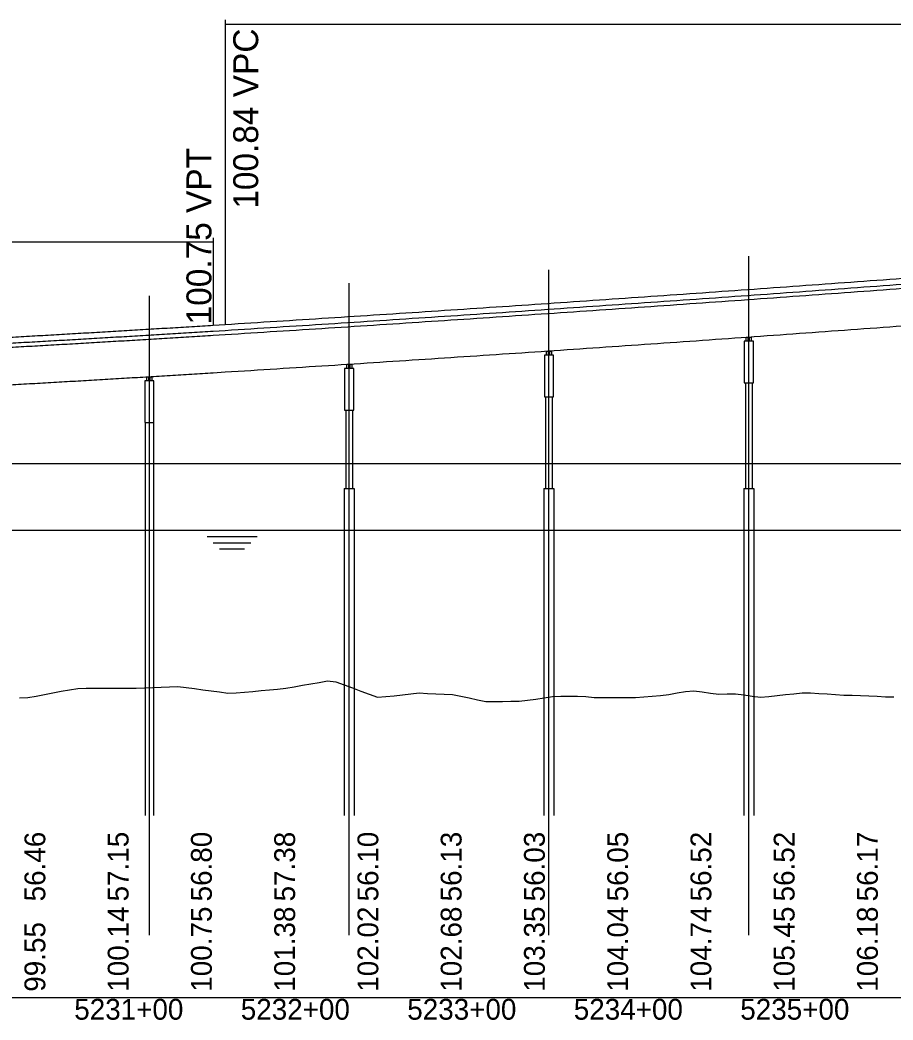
# Model space of a CAD drawing. Extents: x 2121671 to 2169879, y 557274 to 599957.
# Drawn here: x 2152602 to 2153126, y 579173 to 579774 of the extents above; entities that cross this region are included whole.
import ezdxf

# ---------------------------------------------------------------- set-up
doc = ezdxf.new("R2010")
doc.units = 0
for name, color, linetype in [('BR_CENTER LINES', 7, 'Continuous'), ('BR_CONCRETE', 7, 'Continuous'), ('BR_DETAILS', 7, 'Continuous'), ('BR_PRESTRESSED BEAM', 7, 'Continuous'), ('RD_DDB_Profile_Elev', 7, 'Continuous'), ('RD_DDB_Profile_EX', 7, 'Continuous'), ('RD_DDB_Profile_PR', 7, 'Continuous'), ('RD_DDB_StaTX', 7, 'Continuous'), ('RD_DDB_StripGrade', 7, 'Continuous'), ('RD_DDB_VCLbl', 7, 'Continuous'), ('RD_GPK_Profile_Cell', 7, 'Continuous')]:
    doc.layers.add(name, color=color, linetype=linetype)

msp = doc.modelspace()

# ---------------------------------------------------------------- linework, layer by layer
at = {"layer": 'BR_CENTER LINES'}
for p, q in [((2153039.43, 579224.3), (2153039.43, 579632.04)), ((2152919.43, 579224.3), (2152919.43, 579623.69)), ((2152799.43, 579224.3), (2152799.43, 579615.74)), ((2152679.43, 579224.3), (2152679.43, 579608.2))]:
    msp.add_line(p, q, dxfattribs=at)
at = {"layer": 'BR_CONCRETE'}
for p, q in [((2152717.84, 579587.02), (2152724.93, 579587.46)), ((2153037.43, 579555.89), (2153037.43, 579492.43)), ((2153041.43, 579555.89), (2153041.43, 579492.43)), ((2152917.43, 579547.54), (2152917.43, 579492.43)), ((2152921.43, 579547.54), (2152921.43, 579492.43)), ((2152797.43, 579539.6), (2152797.43, 579492.43)), ((2152801.43, 579539.6), (2152801.43, 579492.43)), ((2152676.93, 579532.07), (2152676.93, 579296.09)), ((2152681.93, 579532.07), (2152681.93, 579296.09)), ((2152796.43, 579492.43), (2152796.43, 579296.09)), ((2152796.43, 579492.43), (2152802.43, 579492.43)), ((2152802.43, 579492.43), (2152802.43, 579296.09)), ((2152916.43, 579492.43), (2152916.43, 579296.09)), ((2152916.43, 579492.43), (2152922.43, 579492.43)), ((2152922.43, 579492.43), (2152922.43, 579296.09)), ((2153036.43, 579492.43), (2153036.43, 579296.09)), ((2153036.43, 579492.43), (2153042.43, 579492.43)), ((2153042.43, 579492.43), (2153042.43, 579296.09))]:
    msp.add_line(p, q, dxfattribs=at)
for points in [[(2153036.68, 579555.89), (2153042.18, 579555.89), (2153042.18, 579580.89), (2153036.68, 579580.89)], [(2152916.68, 579547.54), (2152922.18, 579547.54), (2152922.18, 579572.54), (2152916.68, 579572.54)], [(2152796.68, 579539.6), (2152802.18, 579539.6), (2152802.18, 579564.6), (2152796.68, 579564.6)], [(2152676.68, 579532.07), (2152682.18, 579532.07), (2152682.18, 579557.07), (2152676.68, 579557.07)]]:
    msp.add_lwpolyline(points, close=True, dxfattribs=at)
for points in [[(2152724.93, 579587.46), (2152755.93, 579589.42), (2152786.93, 579591.39), (2152817.93, 579593.4), (2152848.93, 579595.43), (2152879.93, 579597.48), (2152910.93, 579599.57), (2152941.93, 579601.68), (2152972.93, 579603.82), (2153003.93, 579605.98), (2153034.93, 579608.17), (2153065.93, 579610.39), (2153096.93, 579612.64), (2153127.93, 579614.91), (2153158.93, 579617.21), (2153189.93, 579619.53), (2153220.93, 579621.88), (2153251.93, 579624.26), (2153282.93, 579626.67), (2153313.93, 579629.1), (2153344.93, 579631.56), (2153375.93, 579634.04), (2153406.93, 579636.55), (2153437.93, 579639.09), (2153468.93, 579641.66), (2153499.93, 579644.25), (2153530.93, 579646.87), (2153561.93, 579649.52), (2153592.93, 579652.19), (2153623.93, 579654.89), (2153654.93, 579657.61), (2153685.93, 579660.37), (2153716.93, 579663.15), (2153747.93, 579665.95), (2153778.93, 579668.79), (2153809.93, 579671.65), (2153840.93, 579674.53), (2153871.93, 579677.45), (2153902.93, 579680.39), (2153933.93, 579683.35), (2153964.93, 579686.35), (2153995.93, 579689.37), (2154026.93, 579692.42), (2154057.93, 579695.49), (2154088.93, 579698.59), (2154119.93, 579701.72), (2154150.93, 579704.87), (2154181.93, 579708.05), (2154212.93, 579711.26), (2154243.93, 579714.5), (2154274.93, 579717.76)], [(2152067.84, 579557.94), (2152080.84, 579558.29), (2152093.84, 579558.66), (2152106.84, 579559.03), (2152119.84, 579559.42), (2152132.84, 579559.81), (2152145.84, 579560.21), (2152158.84, 579560.62), (2152171.84, 579561.04), (2152184.84, 579561.47), (2152197.84, 579561.91), (2152210.84, 579562.36), (2152223.84, 579562.82), (2152236.84, 579563.28), (2152249.84, 579563.76), (2152262.84, 579564.24), (2152275.84, 579564.74), (2152288.84, 579565.24), (2152301.84, 579565.75), (2152314.84, 579566.27), (2152327.84, 579566.8), (2152340.84, 579567.34), (2152353.84, 579567.89), (2152366.84, 579568.45), (2152379.84, 579569.02), (2152392.84, 579569.6), (2152405.84, 579570.18), (2152418.84, 579570.78), (2152431.84, 579571.38), (2152444.84, 579572), (2152457.84, 579572.62), (2152470.84, 579573.25), (2152483.84, 579573.89), (2152496.84, 579574.55), (2152509.84, 579575.21), (2152522.84, 579575.87), (2152535.84, 579576.55), (2152548.84, 579577.24), (2152561.84, 579577.94), (2152574.84, 579578.64), (2152587.84, 579579.36), (2152600.84, 579580.08), (2152613.84, 579580.82), (2152626.84, 579581.56), (2152639.84, 579582.31), (2152652.84, 579583.08), (2152665.84, 579583.85), (2152678.84, 579584.63), (2152691.84, 579585.42), (2152704.84, 579586.21), (2152717.84, 579587.02)]]:
    msp.add_spline(points, degree=3, dxfattribs=at)
at = {"layer": 'BR_DETAILS'}
for points in [[(2153037.93, 579583.39), (2153038.93, 579583.39), (2153038.93, 579580.89), (2153037.93, 579580.89)], [(2153039.93, 579583.39), (2153040.93, 579583.39), (2153040.93, 579580.89), (2153039.93, 579580.89)], [(2152917.93, 579575.04), (2152918.93, 579575.04), (2152918.93, 579572.54), (2152917.93, 579572.54)], [(2152919.93, 579575.04), (2152920.93, 579575.04), (2152920.93, 579572.54), (2152919.93, 579572.54)], [(2152797.93, 579567.1), (2152798.93, 579567.1), (2152798.93, 579564.6), (2152797.93, 579564.6)], [(2152799.93, 579567.1), (2152800.93, 579567.1), (2152800.93, 579564.6), (2152799.93, 579564.6)], [(2152677.93, 579559.57), (2152678.93, 579559.57), (2152678.93, 579557.07), (2152677.93, 579557.07)], [(2152679.93, 579559.57), (2152680.93, 579559.57), (2152680.93, 579557.07), (2152679.93, 579557.07)]]:
    msp.add_lwpolyline(points, close=True, dxfattribs=at)
at = {"layer": 'BR_PRESTRESSED BEAM'}
for p, q in [((2152717.84, 579584.52), (2152724.93, 579584.96)), ((2152717.84, 579562.02), (2152724.93, 579562.46))]:
    msp.add_line(p, q, dxfattribs=at)
for points in [[(2152724.93, 579584.96), (2152755.93, 579586.92), (2152786.93, 579588.89), (2152817.93, 579590.9), (2152848.93, 579592.93), (2152879.93, 579594.98), (2152910.93, 579597.07), (2152941.93, 579599.18), (2152972.93, 579601.32), (2153003.93, 579603.48), (2153034.93, 579605.67), (2153065.93, 579607.89), (2153096.93, 579610.14), (2153127.93, 579612.41), (2153158.93, 579614.71), (2153189.93, 579617.03), (2153220.93, 579619.38), (2153251.93, 579621.76), (2153282.93, 579624.17), (2153313.93, 579626.6), (2153344.93, 579629.06), (2153375.93, 579631.54), (2153406.93, 579634.05), (2153437.93, 579636.59), (2153468.93, 579639.16), (2153499.93, 579641.75), (2153530.93, 579644.37), (2153561.93, 579647.02), (2153592.93, 579649.69), (2153623.93, 579652.39), (2153654.93, 579655.11), (2153685.93, 579657.87), (2153716.93, 579660.65), (2153747.93, 579663.45), (2153778.93, 579666.29), (2153809.93, 579669.15), (2153840.93, 579672.03), (2153871.93, 579674.95), (2153902.93, 579677.89), (2153933.93, 579680.85), (2153964.93, 579683.85), (2153995.93, 579686.87), (2154026.93, 579689.92), (2154057.93, 579692.99), (2154088.93, 579696.09), (2154119.93, 579699.22), (2154150.93, 579702.37), (2154181.93, 579705.55), (2154212.93, 579708.76), (2154243.93, 579712), (2154274.93, 579715.26)], [(2152724.93, 579562.46), (2152755.93, 579564.42), (2152786.93, 579566.39), (2152817.93, 579568.4), (2152848.93, 579570.43), (2152879.93, 579572.48), (2152910.93, 579574.57), (2152941.93, 579576.68), (2152972.93, 579578.82), (2153003.93, 579580.98), (2153034.93, 579583.17), (2153065.93, 579585.39), (2153096.93, 579587.64), (2153127.93, 579589.91), (2153158.93, 579592.21), (2153189.93, 579594.53), (2153220.93, 579596.88), (2153251.93, 579599.26), (2153282.93, 579601.67), (2153313.93, 579604.1), (2153344.93, 579606.56), (2153375.93, 579609.04), (2153406.93, 579611.55), (2153437.93, 579614.09), (2153468.93, 579616.66), (2153499.93, 579619.25), (2153530.93, 579621.87), (2153561.93, 579624.52), (2153592.93, 579627.19), (2153623.93, 579629.89), (2153654.93, 579632.61), (2153685.93, 579635.37), (2153716.93, 579638.15), (2153747.93, 579640.95), (2153778.93, 579643.79), (2153809.93, 579646.65), (2153840.93, 579649.53), (2153871.93, 579652.45), (2153902.93, 579655.39), (2153933.93, 579658.35), (2153964.93, 579661.35), (2153995.93, 579664.37), (2154026.93, 579667.42), (2154057.93, 579670.49), (2154088.93, 579673.59), (2154119.93, 579676.72), (2154150.93, 579679.87), (2154181.93, 579683.05), (2154212.93, 579686.26), (2154243.93, 579689.5), (2154274.93, 579692.76)], [(2152067.84, 579555.44), (2152080.84, 579555.79), (2152093.84, 579556.16), (2152106.84, 579556.53), (2152119.84, 579556.92), (2152132.84, 579557.31), (2152145.84, 579557.71), (2152158.84, 579558.12), (2152171.84, 579558.54), (2152184.84, 579558.97), (2152197.84, 579559.41), (2152210.84, 579559.86), (2152223.84, 579560.32), (2152236.84, 579560.78), (2152249.84, 579561.26), (2152262.84, 579561.74), (2152275.84, 579562.24), (2152288.84, 579562.74), (2152301.84, 579563.25), (2152314.84, 579563.77), (2152327.84, 579564.3), (2152340.84, 579564.84), (2152353.84, 579565.39), (2152366.84, 579565.95), (2152379.84, 579566.52), (2152392.84, 579567.1), (2152405.84, 579567.68), (2152418.84, 579568.28), (2152431.84, 579568.88), (2152444.84, 579569.5), (2152457.84, 579570.12), (2152470.84, 579570.75), (2152483.84, 579571.39), (2152496.84, 579572.05), (2152509.84, 579572.71), (2152522.84, 579573.37), (2152535.84, 579574.05), (2152548.84, 579574.74), (2152561.84, 579575.44), (2152574.84, 579576.14), (2152587.84, 579576.86), (2152600.84, 579577.58), (2152613.84, 579578.32), (2152626.84, 579579.06), (2152639.84, 579579.81), (2152652.84, 579580.58), (2152665.84, 579581.35), (2152678.84, 579582.13), (2152691.84, 579582.92), (2152704.84, 579583.71), (2152717.84, 579584.52)], [(2152067.84, 579532.94), (2152080.84, 579533.29), (2152093.84, 579533.66), (2152106.84, 579534.03), (2152119.84, 579534.42), (2152132.84, 579534.81), (2152145.84, 579535.21), (2152158.84, 579535.62), (2152171.84, 579536.04), (2152184.84, 579536.47), (2152197.84, 579536.91), (2152210.84, 579537.36), (2152223.84, 579537.82), (2152236.84, 579538.28), (2152249.84, 579538.76), (2152262.84, 579539.24), (2152275.84, 579539.74), (2152288.84, 579540.24), (2152301.84, 579540.75), (2152314.84, 579541.27), (2152327.84, 579541.8), (2152340.84, 579542.34), (2152353.84, 579542.89), (2152366.84, 579543.45), (2152379.84, 579544.02), (2152392.84, 579544.6), (2152405.84, 579545.18), (2152418.84, 579545.78), (2152431.84, 579546.38), (2152444.84, 579547), (2152457.84, 579547.62), (2152470.84, 579548.25), (2152483.84, 579548.89), (2152496.84, 579549.55), (2152509.84, 579550.21), (2152522.84, 579550.87), (2152535.84, 579551.55), (2152548.84, 579552.24), (2152561.84, 579552.94), (2152574.84, 579553.64), (2152587.84, 579554.36), (2152600.84, 579555.08), (2152613.84, 579555.82), (2152626.84, 579556.56), (2152639.84, 579557.31), (2152652.84, 579558.08), (2152665.84, 579558.85), (2152678.84, 579559.63), (2152691.84, 579560.42), (2152704.84, 579561.21), (2152717.84, 579562.02)]]:
    msp.add_spline(points, degree=3, dxfattribs=at)
at = {"layer": 'RD_DDB_Profile_Elev'}
for p, q in [((2151922.43, 579507.43), (2155499.43, 579507.43)), ((2151953.51, 579467.43), (2156316.65, 579467.43)), ((2152714.09, 579463.68), (2152744.09, 579463.68)), ((2152717.84, 579459.93), (2152740.34, 579459.93)), ((2152721.59, 579456.18), (2152736.59, 579456.18))]:
    msp.add_line(p, q, dxfattribs=at)
at = {"layer": 'RD_DDB_Profile_EX'}
for points in [[(2152721.48, 579370.34), (2152726.48, 579369.68), (2152731.48, 579369.8), (2152736.48, 579370.24), (2152741.48, 579370.67), (2152746.48, 579371.11), (2152751.48, 579371.54), (2152756.48, 579371.98), (2152761.48, 579372.59), (2152766.48, 579373.46), (2152771.48, 579374.33), (2152776.48, 579375.19), (2152781.48, 579376.06), (2152786.48, 579376.93), (2152791.48, 579376.38), (2152796.48, 579374.55), (2152801.48, 579372.72), (2152806.48, 579370.89), (2152811.48, 579369.06), (2152816.48, 579367.23), (2152821.48, 579367.5), (2152826.48, 579368.08), (2152831.48, 579368.65), (2152836.48, 579369.23), (2152841.48, 579369.72), (2152846.48, 579369.48), (2152851.48, 579369.25), (2152856.48, 579369.02), (2152861.48, 579368.79), (2152866.48, 579367.79), (2152871.48, 579366.73), (2152876.48, 579365.67), (2152881.48, 579364.61), (2152886.48, 579364.54), (2152891.48, 579364.63), (2152896.48, 579364.73), (2152901.48, 579364.82), (2152906.48, 579365.3), (2152911.48, 579366.03), (2152916.48, 579366.76), (2152921.48, 579367.5), (2152926.48, 579367.88), (2152931.48, 579367.8), (2152936.48, 579367.72), (2152941.48, 579367.65), (2152946.48, 579366.91), (2152951.48, 579366.96), (2152956.48, 579367.02), (2152961.48, 579367.07), (2152966.48, 579367.06), (2152971.48, 579367.08), (2152976.48, 579367.44), (2152981.48, 579367.8), (2152986.48, 579368.16), (2152991.48, 579368.87), (2152996.48, 579369.75), (2153001.48, 579370.63), (2153006.48, 579371.07), (2153011.48, 579370.35), (2153016.48, 579369.62), (2153021.48, 579368.9), (2153026.48, 579369.28), (2153031.48, 579369.19), (2153036.48, 579368.53), (2153041.48, 579367.87), (2153046.48, 579367.21), (2153051.48, 579367.66), (2153056.48, 579368.2), (2153061.48, 579368.74), (2153066.48, 579369.29), (2153071.48, 579369.76), (2153076.48, 579369.82), (2153081.48, 579369.48), (2153086.48, 579369.14), (2153091.48, 579368.8), (2153096.48, 579368.46), (2153101.48, 579368.46), (2153106.48, 579368.21), (2153111.48, 579367.97), (2153116.48, 579367.73), (2153121.48, 579367.48), (2153126.48, 579367.37)], [(2152601.48, 579366.77), (2152606.48, 579366.92), (2152611.48, 579367.88), (2152616.48, 579368.83), (2152621.48, 579369.78), (2152626.48, 579370.74), (2152631.48, 579371.69), (2152636.48, 579372.5), (2152641.48, 579372.54), (2152646.48, 579372.57), (2152651.48, 579372.6), (2152656.48, 579372.63), (2152661.48, 579372.66), (2152666.48, 579372.56), (2152671.48, 579372.65), (2152676.48, 579372.83), (2152681.48, 579373), (2152686.48, 579373.18), (2152691.48, 579373.35), (2152696.48, 579373.53), (2152701.48, 579372.98), (2152706.48, 579372.32), (2152711.48, 579371.66), (2152716.48, 579371), (2152721.48, 579370.34)]]:
    msp.add_lwpolyline(points, dxfattribs=at)
at = {"layer": 'RD_DDB_Profile_PR'}
msp.add_line((2152717.84, 579590.56), (2152724.93, 579591.01), dxfattribs=at)
for points in [[(2152724.93, 579591.01), (2152755.93, 579592.96), (2152786.93, 579594.93), (2152817.93, 579596.94), (2152848.93, 579598.97), (2152879.93, 579601.03), (2152910.93, 579603.11), (2152941.93, 579605.22), (2152972.93, 579607.36), (2153003.93, 579609.52), (2153034.93, 579611.71), (2153065.93, 579613.93), (2153096.93, 579616.18), (2153127.93, 579618.45), (2153158.93, 579620.75), (2153189.93, 579623.07), (2153220.93, 579625.42), (2153251.93, 579627.8), (2153282.93, 579630.21), (2153313.93, 579632.64), (2153344.93, 579635.1), (2153375.93, 579637.58), (2153406.93, 579640.1), (2153437.93, 579642.63), (2153468.93, 579645.2), (2153499.93, 579647.79), (2153530.93, 579650.41), (2153561.93, 579653.06), (2153592.93, 579655.73), (2153623.93, 579658.43), (2153654.93, 579661.16), (2153685.93, 579663.91), (2153716.93, 579666.69), (2153747.93, 579669.5), (2153778.93, 579672.33), (2153809.93, 579675.19), (2153840.93, 579678.08), (2153871.93, 579680.99), (2153902.93, 579683.93), (2153933.93, 579686.9), (2153964.93, 579689.89), (2153995.93, 579692.91), (2154026.93, 579695.96), (2154057.93, 579699.03), (2154088.93, 579702.13), (2154119.93, 579705.26), (2154150.93, 579708.41), (2154181.93, 579711.59), (2154212.93, 579714.8), (2154243.93, 579718.04), (2154274.93, 579721.3)], [(2152067.84, 579561.48), (2152080.84, 579561.84), (2152093.84, 579562.2), (2152106.84, 579562.57), (2152119.84, 579562.96), (2152132.84, 579563.35), (2152145.84, 579563.75), (2152158.84, 579564.16), (2152171.84, 579564.58), (2152184.84, 579565.01), (2152197.84, 579565.45), (2152210.84, 579565.9), (2152223.84, 579566.36), (2152236.84, 579566.82), (2152249.84, 579567.3), (2152262.84, 579567.78), (2152275.84, 579568.28), (2152288.84, 579568.78), (2152301.84, 579569.29), (2152314.84, 579569.81), (2152327.84, 579570.35), (2152340.84, 579570.89), (2152353.84, 579571.44), (2152366.84, 579571.99), (2152379.84, 579572.56), (2152392.84, 579573.14), (2152405.84, 579573.72), (2152418.84, 579574.32), (2152431.84, 579574.93), (2152444.84, 579575.54), (2152457.84, 579576.16), (2152470.84, 579576.79), (2152483.84, 579577.44), (2152496.84, 579578.09), (2152509.84, 579578.75), (2152522.84, 579579.42), (2152535.84, 579580.1), (2152548.84, 579580.78), (2152561.84, 579581.48), (2152574.84, 579582.19), (2152587.84, 579582.9), (2152600.84, 579583.63), (2152613.84, 579584.36), (2152626.84, 579585.1), (2152639.84, 579585.86), (2152652.84, 579586.62), (2152665.84, 579587.39), (2152678.84, 579588.17), (2152691.84, 579588.96), (2152704.84, 579589.76), (2152717.84, 579590.56)]]:
    msp.add_spline(points, degree=3, dxfattribs=at)
at = {"layer": 'RD_DDB_VCLbl'}
for p, q in [((2152724.93, 579773.8), (2152724.93, 579591.01)), ((2152724.93, 579771.3), (2154274.93, 579771.3)), ((2152067.84, 579640.56), (2152717.84, 579640.56)), ((2152717.84, 579643.06), (2152717.84, 579590.56))]:
    msp.add_line(p, q, dxfattribs=at)
at = {"layer": 'RD_GPK_Profile_Cell'}
msp.add_line((2151067.93, 579186.83), (2157367.93, 579186.83), dxfattribs=at)

# ---------------------------------------------------------------- texts
at = {"layer": 'RD_DDB_StaTX'}
for s, p in [('5231+00', (2152634.32, 579173.53)), ('5232+00', (2152734.32, 579173.53)), ('5233+00', (2152834.32, 579173.53)), ('5234+00', (2152934.32, 579173.53)), ('5235+00', (2153034.32, 579173.53))]:
    msp.add_text(s, height=12.5, dxfattribs=at).set_placement(p)
at = {"layer": 'RD_DDB_StripGrade'}
for s, height, p in [('100.84 VPC', 15, (2152744.79, 579660.49)), ('100.75 VPT', 15, (2152716.69, 579591.03)), ('56.46', 12.5, (2152616.93, 579244.56)), ('57.15', 12.5, (2152666.93, 579244.56)), ('56.80', 12.5, (2152716.93, 579244.56)), ('57.38', 12.5, (2152766.93, 579244.56)), ('56.10', 12.5, (2152816.93, 579244.56)), ('56.13', 12.5, (2152866.93, 579244.56)), ('56.03', 12.5, (2152916.93, 579244.56)), ('56.05', 12.5, (2152966.93, 579244.56)), ('56.52', 12.5, (2153016.93, 579244.56)), ('56.52', 12.5, (2153066.93, 579244.56)), ('56.17', 12.5, (2153116.93, 579244.56)), ('100.14', 12.5, (2152666.93, 579190.33)), ('100.75', 12.5, (2152716.93, 579190.33)), ('101.38', 12.5, (2152766.93, 579190.33)), ('102.02', 12.5, (2152816.93, 579190.33)), ('102.68', 12.5, (2152866.93, 579190.33)), ('103.35', 12.5, (2152916.93, 579190.33)), ('104.04', 12.5, (2152966.93, 579190.33)), ('104.74', 12.5, (2153016.93, 579190.33)), ('105.45', 12.5, (2153066.93, 579190.33)), ('106.18', 12.5, (2153116.93, 579190.33)), ('99.55', 12.5, (2152616.93, 579190.33))]:
    msp.add_text(s, height=height, rotation=90, dxfattribs=at).set_placement(p)

doc.saveas('drawing.dxf')
